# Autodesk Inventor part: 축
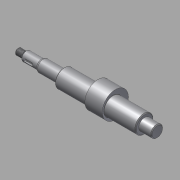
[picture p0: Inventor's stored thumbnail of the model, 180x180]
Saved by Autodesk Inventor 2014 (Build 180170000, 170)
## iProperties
Created: 2015-12
Part Number: 축
Document SubType Name: Modeling
Designer: mdu
Density: 1 g/cm^3
Material: 강철, 연강
Appearance: 강철
Mass: 62.304 g
Surface Area: 127.382 cm^2
Volume: 62.304 cm^3
Author: mdu
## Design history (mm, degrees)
sketch "스케치1"
  geometry: L1 (62, 100.9)-(62, 67.1) reference; L2 (51, 101.2)-(51, 84) reference; L3 (-51, 84)-(-51, 101.2) reference; L4 (-62, 67.1)-(-62, 100.9) reference; L5 (-51.6, 91.5)-(-61.4, 91.5) reference; L6 (51.6, 91.5)-(61.4, 91.5) reference; L7 (67, 84)-(-109, 84); L8 (-77, 64.201)-(-77, 103.799) reference; L9 (67, 84)-(67, 91.5); L10 (67, 91.5)-(51, 91.5); L11 (51, 91.5)-(51, 95.5); L12 (51, 95.5)-(-51, 95.5); L13 (-51, 95.5)-(-51, 91.5); L14 (-51, 91.5)-(-79, 91.5); L15 (-79, 91.5)-(-79, 90); L16 (-79, 90)-(-99, 90); L17 (-99, 90)-(-99, 87); L18 (-100.5, 88)-(-109, 88); L19 (-109, 88)-(-109, 84); L20 (-99, 87)-(-100.5, 87); L21 (-100.5, 87)-(-100.5, 88); 2 further points
  constraints: 32 end point, 7 parallel, 6 point on line, 5 perpendicular, 2 collinear, 2 horizontal, 1 midpoint, 4 other
  dimensions: "d0" = 5 distance from line of L7.start L1; "d2" = 2 distance between parallel lines of L15 L8; "d3" = 23 diameter of L12 L7; "d4" = 12 diameter of L16 L7; "d5" = 1.5 distance of L17.end L20.end; "d6" = 6 diameter of L20 L7; "d7" = 20 distance of L15.end L16.end; "d8" = 10 distance between parallel lines of L17 L19; "d9" = 8 diameter of L18 L7
revolve "회전1" sketch "스케치1" stored, may be unused: angle "d10" = 90 deg
sketch "스케치2"
  geometry: C1 r 11.5 at (84, 0) reference; C2 r 11.5 at (84, 0) reference; C3 r 16.5 at (87, 0); 1 further point
  constraints: 1 centre point, 1 horizontal alignment
  dimensions: "d11" = 33 diameter of C3; "d12" = 3 distance of C3.centre C1.centre
extrude "돌출1" join sketch "스케치2" stored distance "d13" = 22; taper "d14" = 0 deg
chamfer "모따기1" distance "d15" = 1; stored, may be unused: second distance "d16" = 2, angle "d17" = 45 deg
feature "스레드1" dims "d18" = 10, "d19" = 0
node "작업 평면1"
sketch "스케치3"
  geometry: L1 (-5, -2)-(3, -2); L2 (3, 2)-(-5, 2); L3 (-10, -5)-(-10, 5) reference; A1 r 2 centre (3, 0) between (3, -2) and (3, 2); A2 r 2 centre (-5, 0) between (-5, 2) and (-5, -2); 2 further points
  constraints: 4 end point, 4 point on circle, 4 tangent, 2 centre point, 1 horizontal, 1 horizontal alignment, 1 midpoint, 1 parallel
  dimensions: "d20" = 4 distance between parallel lines of L1 L2; "d21" = 12 dimension on A1 A2; "d22" = 3 distance edge to line of A2 L3
extrude "돌출2" cut sketch "스케치3" distance "d23" = 2.5; taper "d24" = 0 deg
fillet "모깎기1" dims "d25" = 0.3
fillet "모깎기2" dims "d26" = 3
node "솔리드1"
node "참조1"
node "참조2"
node "참조3"
node "참조4"
node "참조5"
node "투영된 루프1"
